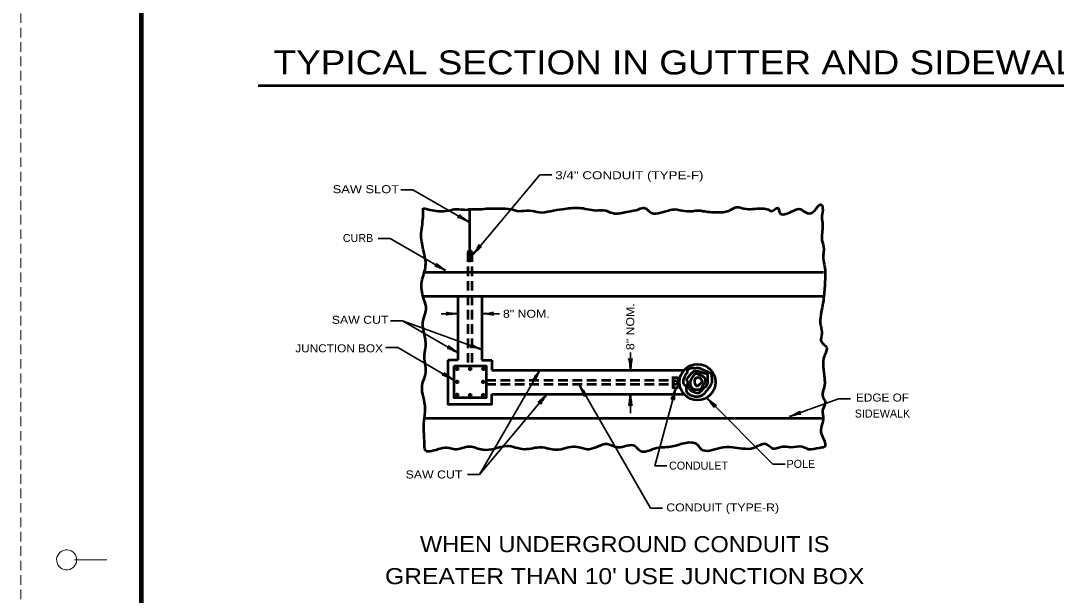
# Model space of a CAD drawing. Extents: x -58 to 622, y -372 to 68.
# Drawn here: x -58.5 to 200.3, y -243.1 to -99.4 of the extents above; entities that cross this region are included whole.
import ezdxf
from ezdxf.enums import TextEntityAlignment as Align

# ---------------------------------------------------------------- set-up
doc = ezdxf.new("R2010")
doc.units = 0
doc.header["$LTSCALE"] = 0.8
doc.linetypes.add('LONG_DASHED', pattern=[7.5, 6, -1.5])
doc.linetypes.add('MEDIUM_DASHED', pattern=[4.5, 3, -1.5])
doc.layers.add('1', color=7, linetype='Continuous', lineweight=35)
doc.layers.add('61', color=7, linetype='Continuous', lineweight=35)

msp = doc.modelspace()

# ---------------------------------------------------------------- linework, layer by layer
at = {"layer": '1', "linetype": 'MEDIUM_DASHED', "lineweight": 13}
msp.add_line((-58.4297, 67.9933), (-58.4898, -372.0467), dxfattribs=at)
at = {"layer": '1', "lineweight": 53}
for p, q in [((0.8544, -115.6087), (216.8702, -115.6087)), ((53.7427, -159.7717), (53.7427, -146.2717)), ((42.0595, -162.3067), (142.0595, -162.3067)), ((42.0595, -168.3067), (142.0595, -168.3067)), ((50.7427, -168.3067), (50.7427, -184.3067)), ((56.7427, -168.3067), (56.7427, -184.3067)), ((50.7427, -184.3067), (48.2427, -184.3067)), ((56.7427, -184.3067), (59.2427, -184.3067)), ((59.2427, -184.3067), (59.2427, -186.8067)), ((59.2427, -186.8067), (107.227, -186.8067)), ((104.3797, -188.6473), (105.8, -188.6473)), ((104.418, -188.3786), (104.418, -191.3786)), ((105.8, -188.6473), (105.8, -191.1473)), ((104.3797, -191.1473), (105.8, -191.1473)), ((59.2427, -192.8067), (93.8582, -192.8067)), ((93.779, -192.8067), (107.2712, -192.8067)), ((42.3769, -198.8067), (142.0708, -198.8067))]:
    msp.add_line(p, q, dxfattribs=at)
at = {"layer": '1', "linetype": 'MEDIUM_DASHED', "lineweight": 53}
for p, q in [((53.2427, -157.3067), (53.2427, -185.7174)), ((54.2427, -157.3067), (54.2427, -185.7174)), ((57.7928, -189.3067), (104.3989, -189.3067)), ((57.7928, -190.3067), (104.4088, -190.3067))]:
    msp.add_line(p, q, dxfattribs=at)
at = {"layer": '1'}
for p, q in [((50.6812, -172.6817), (46.602, -172.6817)), ((61.102, -172.6817), (56.7814, -172.6817)), ((36.8893, -174.4334), (33.8893, -174.4334)), ((35.701, -181.1674), (32.701, -181.1674)), ((35.701, -181.1674), (49.5574, -189.1674)), ((93.8582, -182.3864), (93.8582, -186.7438)), ((93.8582, -192.7647), (93.8582, -197.5024)), ((56.1208, -212.9046), (53.1208, -212.9046))]:
    msp.add_line(p, q, dxfattribs=at)
for points in [[(54.5286, -157.8822), (71.241, -137.9651), (74.241, -137.9651)], [(53.3747, -149.6886), (39.5183, -141.6886), (36.5183, -141.6886)], [(47.6707, -161.889), (33.8143, -153.889), (30.8142, -153.889)], [(56.6229, -181.6158), (36.8893, -174.4334), (50.7458, -182.4334)], [(71.1208, -186.9238), (56.1208, -212.9046), (72.9849, -192.8067)], [(81.2615, -190.7265), (98.8817, -221.2457), (101.8817, -221.2457)], [(105.1616, -191.3462), (99.9852, -210.6647), (102.9852, -210.6647)], [(113.0107, -193.8116), (129.4815, -210.2824), (132.4815, -210.2824)], [(133.6284, -198.3907), (145.8444, -193.9445), (148.8444, -193.9445)]]:
    msp.add_lwpolyline(points, dxfattribs=at)
at = {"layer": '1', "lineweight": 53}
msp.add_lwpolyline([(48.2427, -184.3067), (48.2427, -195.3067), (59.2427, -195.3067), (59.2427, -192.8067)], dxfattribs=at)
msp.add_lwpolyline([(49.7928, -185.7174), (57.7928, -185.7174), (57.7928, -193.7174), (49.7928, -193.7174)], close=True, dxfattribs=at)
for centre, radius in [((50.5838, -186.4463), 0.25), ((53.8318, -186.4463), 0.25), ((57.1194, -186.4463), 0.25), ((110.6031, -189.7819), 4.5), ((50.5838, -189.6942), 0.25), ((57.0402, -189.6942), 0.25), ((105.1089, -189.8757), 0.5), ((50.5838, -192.9818), 0.25), ((53.8318, -193.0215), 0.25), ((57.0797, -193.0215), 0.25)]:
    msp.add_circle(centre, radius, dxfattribs=at)
at = {"layer": '1', "linetype": 'LONG_DASHED', "lineweight": 53}
msp.add_arc((53.7427, -157.4507), 0.5203, 16.07383, 163.92617, dxfattribs=at)
at = {"layer": '1', "lineweight": 40}
for centre, major_axis, ratio, start_param, end_param in [((52.2916, -149.3823), (1.6245, -0.7576), 0.122415, 0.89635335, 3.14159265), ((52.2916, -149.3823), (1.6245, -0.7576), 0.122415, 0.89635335, 3.14159265), ((52.5102, -148.9451), (1.4333, -1.0303), 0.07063, 3.14071475, 5.41810995), ((52.5102, -148.9451), (1.4333, -1.0303), 0.07063, 3.14071475, 5.41810995), ((55.0183, -156.8687), (-1.0282, -1.4683), 0.122415, 0.89635335, 3.14159265), ((55.0183, -156.8687), (-1.0282, -1.4683), 0.122415, 0.89635335, 3.14159265), ((55.4109, -157.1599), (1.2636, 1.2326), 0.07063, 6.28230741, 8.55970261), ((55.4109, -157.1599), (1.2636, 1.2326), 0.07063, 6.28230741, 8.55970261), ((46.8061, -161.1455), (1.4333, -1.0303), 0.07063, 3.14071475, 5.41810995), ((46.8061, -161.1455), (1.4333, -1.0303), 0.07063, 3.14071475, 5.41810995), ((46.5875, -161.5827), (1.6245, -0.7576), 0.122415, 0.89635335, 3.14159265), ((46.5875, -161.5827), (1.6245, -0.7576), 0.122415, 0.89635335, 3.14159265), ((49.59, -172.958), (1.7857, 0.1562), 0.122415, 0.89635335, 3.14159265), ((49.59, -172.958), (1.7857, 0.1562), 0.122415, 0.89635335, 3.14159265), ((49.5607, -172.4701), (1.7565, -0.1757), 0.07063, 3.14071475, 5.41810995), ((49.5607, -172.4701), (1.7565, -0.1757), 0.07063, 3.14071475, 5.41810995), ((57.9019, -172.8933), (1.7565, -0.1757), 0.07063, 6.28230741, 8.55970261), ((57.9019, -172.8933), (1.7565, -0.1757), 0.07063, 6.28230741, 8.55970261), ((57.8726, -172.4054), (-1.7857, -0.1562), 0.122415, 0.89635335, 3.14159265), ((57.8726, -172.4054), (-1.7857, -0.1562), 0.122415, 0.89635335, 3.14159265), ((49.8812, -181.6899), (1.4333, -1.0303), 0.07063, 3.14071475, 5.41810995), ((49.8812, -181.6899), (1.4333, -1.0303), 0.07063, 3.14071475, 5.41810995), ((55.503, -181.5023), (1.7314, -0.464), 0.122415, 0.89635335, 3.14159265), ((55.503, -181.5023), (1.7314, -0.464), 0.122415, 0.89635335, 3.14159265), ((55.6424, -181.0338), (-1.5904, 0.7658), 0.07063, 6.28230741, 8.55970261), ((55.6424, -181.0338), (-1.5904, 0.7658), 0.07063, 6.28230741, 8.55970261), ((49.6626, -182.1271), (1.6245, -0.7576), 0.122415, 0.89635335, 3.14159265), ((49.6626, -182.1271), (1.6245, -0.7576), 0.122415, 0.89635335, 3.14159265), ((93.5819, -185.6526), (0.1562, -1.7857), 0.122415, 0.89635335, 3.14159265), ((93.5819, -185.6526), (0.1562, -1.7857), 0.122415, 0.89635335, 3.14159265), ((94.0698, -185.6233), (0.1757, 1.7565), 0.07063, 6.28230741, 8.55970261), ((94.0698, -185.6233), (0.1757, 1.7565), 0.07063, 6.28230741, 8.55970261), ((48.4743, -188.8611), (1.6245, -0.7576), 0.122415, 0.89635335, 3.14159265), ((48.4743, -188.8611), (1.6245, -0.7576), 0.122415, 0.89635335, 3.14159265), ((48.6928, -188.4239), (1.4333, -1.0303), 0.07063, 3.14071475, 5.41810995), ((48.6928, -188.4239), (1.4333, -1.0303), 0.07063, 3.14071475, 5.41810995), ((70.3773, -187.7884), (1.0303, 1.4333), 0.07063, 3.14071475, 5.41810995), ((70.3773, -187.7884), (1.0303, 1.4333), 0.07063, 3.14071475, 5.41810995), ((70.8145, -188.007), (0.7576, 1.6245), 0.122415, 0.89635335, 3.14159265), ((70.8145, -188.007), (0.7576, 1.6245), 0.122415, 0.89635335, 3.14159265), ((81.6385, -191.8027), (-0.7261, 1.609), 0.07063, 3.14071475, 5.41810995), ((81.6385, -191.8027), (-0.7261, 1.609), 0.07063, 3.14071475, 5.41810995), ((82.0464, -191.5334), (-1.0281, 1.4684), 0.122415, 0.89635335, 3.14159265), ((82.0464, -191.5334), (-1.0281, 1.4684), 0.122415, 0.89635335, 3.14159265), ((104.6672, -192.3738), (-0.6243, -1.6511), 0.07063, 6.28230741, 8.55970261), ((104.6672, -192.3738), (-0.6243, -1.6511), 0.07063, 6.28230741, 8.55970261), ((105.146, -192.4718), (0.3113, 1.7653), 0.122415, 0.89635335, 3.14159265), ((105.146, -192.4718), (0.3113, 1.7653), 0.122415, 0.89635335, 3.14159265), ((72.1026, -193.529), (-1.2636, -1.2326), 0.07063, 6.28230741, 8.55970261), ((72.1026, -193.529), (-1.2636, -1.2326), 0.07063, 6.28230741, 8.55970261), ((72.4952, -193.8202), (1.0282, 1.4683), 0.122415, 0.89635335, 3.14159265), ((72.4952, -193.8202), (1.0282, 1.4683), 0.122415, 0.89635335, 3.14159265), ((93.6466, -193.8852), (-0.1757, -1.7565), 0.07063, 6.28230741, 8.55970261), ((93.6466, -193.8852), (-0.1757, -1.7565), 0.07063, 6.28230741, 8.55970261), ((94.1345, -193.8559), (-0.1562, 1.7857), 0.122415, 0.89635335, 3.14159265), ((94.1345, -193.8559), (-0.1562, 1.7857), 0.122415, 0.89635335, 3.14159265), ((113.6534, -194.7535), (1.1178, -1.3662), 0.07063, 6.28230741, 8.55970261), ((113.6534, -194.7535), (1.1178, -1.3662), 0.07063, 6.28230741, 8.55970261), ((113.9776, -194.3878), (-1.3731, 1.1523), 0.122415, 0.89635335, 3.14159265), ((113.9776, -194.3878), (-1.3731, 1.1523), 0.122415, 0.89635335, 3.14159265), ((134.5593, -197.7579), (-1.6246, -0.7575), 0.122415, 0.89635335, 3.14159265), ((134.7537, -198.2064), (1.7106, 0.4357), 0.07063, 6.28230741, 8.55970261)]:
    msp.add_ellipse(centre, major_axis=major_axis, ratio=ratio, start_param=start_param, end_param=end_param, dxfattribs=at)
at = {"layer": '1', "lineweight": 53}
for points in [[(105.117, -146.5359), (106.7013, -146.8528), (109.3948, -147.0112), (110.9792, -146.8528), (111.9297, -147.0112), (115.4153, -147.3282), (118.5841, -146.8528), (120.4853, -146.0607), (122.2281, -146.3775), (126.6643, -146.3775), (128.724, -146.8528), (129.0408, -147.0112), (130.7837, -146.2191), (131.1005, -147.3282), (134.1108, -147.1697), (136.3289, -146.5359), (137.1211, -147.0112), (139.1807, -147.4866), (141.5573, -145.4269), (141.8742, -146.2191), (141.7157, -148.2788), (141.8742, -150.6553), (141.7157, -154.2993), (142.1911, -156.5174), (142.0327, -157.9433), (142.5079, -161.7458), (142.5079, -164.1223), (142.3495, -166.3405), (142.1911, -168.2417), (141.8742, -170.6182), (141.3989, -172.9948), (141.3989, -175.6882), (141.7157, -177.7479), (141.5573, -179.6491), (142.8248, -181.075), (142.3495, -183.1347), (142.0327, -185.9866), (142.3495, -188.8384), (142.3495, -190.5812), (142.0327, -193.7499), (142.5079, -194.5421), (141.8742, -196.7602), (142.0327, -198.9783), (141.3989, -201.8302), (141.8742, -203.4145), (142.3495, -205.9495), (141.082, -206.2664), (138.3886, -206.5832), (136.8042, -205.9495), (133.9524, -206.1079), (131.7343, -205.9495), (129.5162, -206.4248), (127.7733, -205.3157), (124.6047, -206.2664), (121.9112, -206.4248), (119.3762, -206.1079), (116.2075, -206.2664), (111.6129, -206.5832), (110.8207, -205.6327), (103.8495, -205.9495), (99.8886, -206.4248), (96.403, -207.0586), (94.9771, -205.7911), (90.6993, -206.1079), (88.0059, -205.3157), (83.5697, -206.5832), (80.0841, -205.9495), (75.331, -206.7417), (71.5285, -206.1079), (67.4092, -206.5832), (62.973, -205.7911), (59.9627, -206.4248), (56.9524, -206.7417), (53.6253, -205.9495), (49.9812, -206.5832), (48.5553, -206.2664), (46.3372, -206.4248), (42.6932, -206.9002), (42.3762, -204.5236), (42.2178, -201.3548), (42.3762, -198.8199), (42.5347, -195.6512), (41.901, -190.1059), (42.6932, -187.8877), (42.3762, -183.4516), (42.6932, -181.2335), (42.6932, -179.4907), (42.0594, -176.3219), (42.2178, -173.787), (42.8516, -171.5688), (42.2178, -169.0339), (41.7425, -164.5977), (42.6932, -160.6368), (42.2178, -157.1512), (41.5841, -153.1902), (42.0594, -148.4372), (42.0595, -146.3067)], [(42.0595, -146.3067), (43.8023, -146.6944), (45.8619, -147.0112), (48.5553, -146.8528), (50.2981, -146.5359), (52.8331, -146.6944), (54.7343, -146.5359), (56.3187, -146.5359), (58.3783, -146.3775), (61.3886, -146.3775), (63.9236, -146.5359), (65.9832, -147.0112), (68.6767, -146.8528), (71.0532, -147.3282), (73.9051, -147.0112), (76.9153, -146.5359), (81.0347, -146.2191), (83.0944, -146.5359), (85.3125, -146.8528), (87.5306, -146.8528), (88.3227, -147.1697), (90.3824, -147.645), (93.868, -147.0112), (95.6108, -146.6944), (97.0367, -146.2191), (97.9874, -146.5359), (98.6211, -147.1697), (103.3742, -146.8528), (105.117, -146.5359)], [(108.5777, -186.5185), (108.0628, -186.875), (108.0034, -187.39), (107.6469, -187.8851), (107.4687, -188.2614), (107.132, -189.0734), (107.0132, -189.4695), (107.2706, -190.3607), (107.7262, -190.7767), (107.7856, -191.6481), (108.0034, -192.4007), (108.4986, -192.8167), (109.4888, -193.2326), (110.5583, -193.391), (111.1921, -193.292), (111.9645, -192.9355), (112.5587, -192.3611), (113.1726, -191.5887), (113.747, -190.8559), (113.945, -190.4202), (114.2619, -189.8458), (114.3213, -189.3705), (114.2421, -188.6972), (114.1034, -187.8653), (113.6876, -187.5088), (113.2717, -187.3306), (112.9349, -187.1325), (112.1229, -186.7958), (111.4693, -186.4393), (111.0733, -186.3007), (110.3998, -186.3205), (109.9443, -186.3402), (109.4096, -186.3007), (108.9145, -186.3799), (108.6768, -186.4393), (108.4392, -186.5582)], [(109.568, -187.1919), (108.8748, -187.8257), (108.2015, -188.6575), (107.9044, -189.2121), (108.0827, -189.6478), (108.1421, -190.2618), (108.2807, -190.9153), (108.5382, -191.4303), (108.8947, -191.8263), (109.2512, -192.0244), (110.083, -192.3809), (110.4791, -192.4205), (110.9148, -192.4205), (111.2911, -192.2225), (111.6476, -191.9254), (112.0635, -191.4303), (112.5388, -190.9946), (112.7171, -190.8361), (113.133, -190.1825), (113.232, -189.7072), (113.1726, -188.9546), (113.232, -188.1822), (113.0736, -187.8257), (112.7171, -187.6672), (112.3804, -187.6277), (112.1427, -187.5484), (111.7862, -187.4692), (111.1128, -187.2117), (110.7366, -187.1325), (110.2018, -187.1523), (109.7859, -187.0532), (109.4888, -187.2513)], [(110.0632, -187.7267), (109.469, -188.3802), (108.8154, -189.628), (108.7362, -190.2023), (109.0135, -190.9352), (109.3106, -191.3907), (109.7265, -191.5491), (110.7167, -191.6283), (111.7268, -191.1728), (111.9843, -190.5787), (112.4794, -189.9845), (112.6181, -189.4695), (112.5982, -188.9942), (112.3012, -188.6377), (111.9248, -188.3407), (111.5288, -188.1227), (111.2119, -187.9842), (110.8356, -187.9049), (110.6178, -187.7465), (110.3008, -187.6277), (109.9839, -187.7465)], [(110.4395, -188.6773), (109.9443, -189.113), (109.8453, -189.7072), (109.9443, -190.1627), (110.083, -190.4202), (110.2612, -190.6182), (110.4989, -190.7173), (110.9742, -190.4796), (111.2515, -190.2222), (111.7664, -189.7072), (111.7862, -189.4299), (111.6277, -189.1527), (111.4099, -188.8952), (111.0534, -188.7169), (110.7762, -188.6575), (110.5781, -188.6773), (110.3801, -188.8159)]]:
    msp.add_spline(points, degree=3, dxfattribs=at)
at = {"layer": '61', "lineweight": 13}
msp.add_line((-45.0097, -234.1867), (-37.0097, -234.1867), dxfattribs=at)
at = {"layer": '61', "lineweight": 158}
msp.add_lwpolyline([(610.6102, 57.9933), (-28.4297, 57.9933), (-28.4297, -362.0267)], dxfattribs=at)
at = {"layer": '61', "lineweight": 13}
msp.add_arc((-47.012, -234.2054), 2.5, 322.67175, 321.71615, dxfattribs=at)

# ---------------------------------------------------------------- texts
at = {"layer": '1'}
for s, height, width, p in [('TYPICAL SECTION IN GUTTER AND SIDEWALK', 6, 1.15, (4.6777, -112.8777)), ('3/4" CONDUIT (TYPE-F)', 2, 1.25, (75.082, -139.0726)), ('SAW SLOT', 2, 1.2, (19.4669, -142.5584)), ('SAW CUT', 2, 1.15, (19.2293, -175.1987)), ('8" NOM.', 2, 1.15, (62.0101, -173.6934)), ('JUNCTION BOX', 2, 1.1, (10.1186, -182.3288)), ('SAW CUT', 2, 1.15, (37.6883, -213.8599)), ('CONDUIT (TYPE-R)', 2, 1.15, (102.8104, -222.0992))]:
    msp.add_text(s, height=height, dxfattribs=dict(at, width=width)).set_placement(p)
for s, p in [('CURB', (22.0021, -154.7589)), ('POLE', (132.8758, -211.2059)), ('CONDULET', (103.5234, -211.6417))]:
    msp.add_text(s, height=2, dxfattribs=at).set_placement(p)
at = {"layer": '1', "width": 1.15}
msp.add_text('8" NOM.', height=2, rotation=90, dxfattribs=at).set_placement((94.8088, -181.7742))
at = {"layer": '1'}
for s, height, width, p in [('EDGE OF', 2, 1.1, (156.8412, -194.6384)), ('WHEN UNDERGROUND CONDUIT IS', 4, 1.1, (92.4321, -232.2779)), ("GREATER THAN 10' USE JUNCTION BOX", 4, 1.15, (92.4321, -240.2779))]:
    msp.add_text(s, height=height, dxfattribs=dict(at, width=width)).set_placement(p, align=Align.CENTER)
msp.add_text('SIDEWALK', height=2, dxfattribs=at).set_placement((156.8411, -198.6384), align=Align.CENTER)

doc.saveas('drawing.dxf')
